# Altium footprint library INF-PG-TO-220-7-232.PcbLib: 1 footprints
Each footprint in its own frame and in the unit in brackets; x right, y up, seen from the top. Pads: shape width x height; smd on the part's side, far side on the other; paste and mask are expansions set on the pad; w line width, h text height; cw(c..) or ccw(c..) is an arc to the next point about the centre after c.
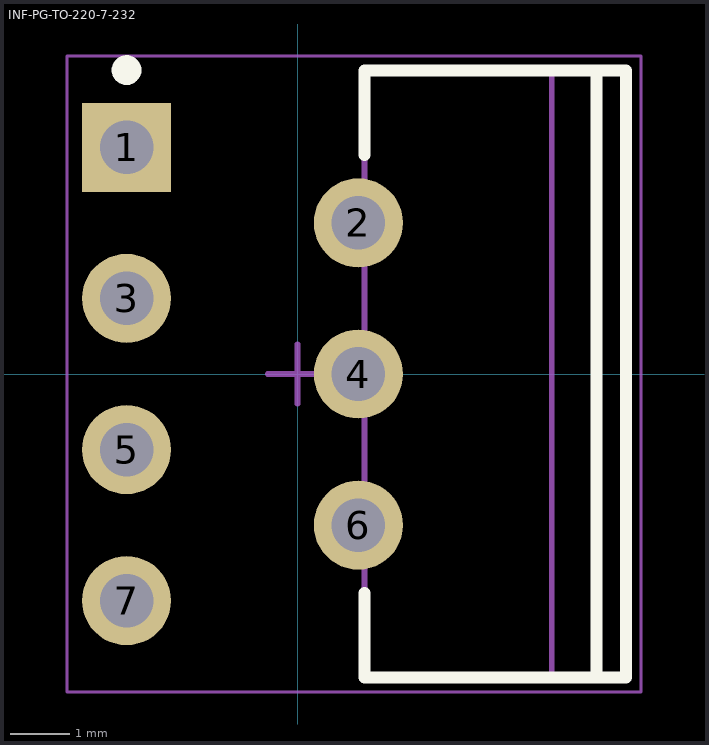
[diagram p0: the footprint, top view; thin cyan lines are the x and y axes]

## INF-PG-TO-220-7-232 [mm] "FM, 7-Leads, Body 10x4.4mm, Pitch 1.27mm"
height 20.02
pads (7):
  rect 1.5x1.5 hole 0.9: 1(-2.875,3.81)
  round 1.5 hole 0.9: 2(1.025,2.54) 3(-2.875,1.27) 4(1.025,0) 5(-2.875,-1.27) 6(1.025,-2.54) 7(-2.875,-3.81)
Top Overlay:
  circle w0.25: c-2.875,5.11 r0.125
  lines w0.2: 1.125,-3.683 1.125,-5.1 5.525,-5.1 5.525,5.1 1.125,5.1 1.125,3.683 ; 5.025,-5.1 5.025,5.1
Mechanical 13:
  lines w0.1: 4.275,-5.1 4.275,5.1 ; 1.125,-5.1 5.525,-5.1 5.525,5.1 1.125,5.1 1.125,-5.1
Mechanical 15:
  lines w0.05: -3.875,-5.35 5.775,-5.35 5.775,5.35 -3.875,5.35 -3.875,-5.35
  lines w0.1: -0.5,0 0.5,0 ; 0,-0.5 0,0.5
3D body: height 20.02, standoff 19.05, extent 4.275,-4.95 5.525,4.95
3D body: height 17.58, standoff 17.22, extent 4.275,-4.95 5.525,-1.825
3D body: height 17.58, standoff 17.22, extent 4.275,1.825 5.525,4.95
3D body: height 17.22, standoff 16.86, extent 4.275,-4.95 5.525,-1.825
3D body: height 17.22, standoff 16.86, extent 4.275,1.825 5.525,4.95
3D body: height 17.92, standoff 17.58, extent 4.275,-4.95 5.525,-1.79
3D body: height 17.92, standoff 17.58, extent 4.275,1.79 5.525,4.95
3D body: height 16.87, standoff 16.52, extent 4.275,-4.95 5.525,-1.79
3D body: height 16.87, standoff 16.52, extent 4.275,1.79 5.525,4.95
3D body: height 18.24, standoff 17.92, extent 4.275,-4.95 5.525,-1.686
3D body: height 18.24, standoff 17.92, extent 4.275,1.686 5.525,4.95
3D body: height 16.53, standoff 16.21, extent 4.275,-4.95 5.525,-1.686
3D body: height 16.53, standoff 16.21, extent 4.275,1.686 5.525,4.95
3D body: height 18.52, standoff 18.23, extent 4.275,-4.95 5.525,-1.517
3D body: height 18.52, standoff 18.23, extent 4.275,1.517 5.525,4.95
3D body: height 16.21, standoff 15.93, extent 4.275,-4.95 5.525,-1.517
3D body: height 16.21, standoff 15.93, extent 4.275,1.517 5.525,4.95
3D body: height 18.74, standoff 18.51, extent 4.275,-4.95 5.525,-1.29
3D body: height 18.74, standoff 18.51, extent 4.275,1.29 5.525,4.95
3D body: height 15.93, standoff 15.7, extent 4.275,-4.95 5.525,-1.29
3D body: height 15.93, standoff 15.7, extent 4.275,1.29 5.525,4.95
3D body: height 18.91, standoff 18.74, extent 4.275,-4.95 5.525,-1.014
3D body: height 18.91, standoff 18.74, extent 4.275,1.014 5.525,4.95
3D body: height 15.71, standoff 15.53, extent 4.275,-4.95 5.525,-1.014
3D body: height 15.71, standoff 15.53, extent 4.275,1.014 5.525,4.95
3D body: height 19.01, standoff 18.91, extent 4.275,-4.95 5.525,-0.698
3D body: height 19.01, standoff 18.91, extent 4.275,0.698 5.525,4.95
3D body: height 15.54, standoff 15.43, extent 4.275,-4.95 5.525,-0.698
3D body: height 15.54, standoff 15.43, extent 4.275,0.698 5.525,4.95
3D body: height 19.05, standoff 19.01, extent 4.275,-4.95 5.525,-0.356
3D body: height 19.05, standoff 19.01, extent 4.275,0.356 5.525,4.95
3D body: height 15.44, standoff 15.4, extent 4.275,-4.95 5.525,-0.356
3D body: height 15.44, standoff 15.4, extent 4.275,0.356 5.525,4.95
3D body: height 15.4, standoff 13.62, extent 4.275,-4.95 5.525,4.95
3D body: height 13.62, standoff 0.92, extent 1.125,-5.1 5.525,5.1
3D body: height 0, standoff -1.6, extent -3.125,-4.11 -2.625,-3.51
3D body: height 0.92, standoff 0.71, extent 3.075,-4.31 3.575,-3.31
3D body: height 0.71, standoff 0.21, extent -3.125,-4.31 3.575,-3.31
3D body: height 0.21, standoff 0, extent -3.125,-4.31 -2.625,-3.31
3D body: height 0, standoff -1.6, extent 2.625,-2.84 3.125,-2.24
3D body: height 0.92, standoff 0.71, extent 3.075,-3.04 3.575,-2.04
3D body: height 0.71, standoff 0.21, extent 2.625,-3.04 3.575,-2.04
3D body: height 0.21, standoff 0, extent 2.625,-3.04 3.125,-2.04
3D body: height 0, standoff -1.6, extent -3.125,-1.57 -2.625,-0.97
3D body: height 0.92, standoff 0.71, extent 3.075,-1.77 3.575,-0.77
3D body: height 0.71, standoff 0.21, extent -3.125,-1.77 3.575,-0.77
3D body: height 0.21, standoff 0, extent -3.125,-1.77 -2.625,-0.77
3D body: height 0, standoff -1.6, extent 2.625,-0.3 3.125,0.3
3D body: height 0.92, standoff 0.71, extent 3.075,-0.5 3.575,0.5
3D body: height 0.71, standoff 0.21, extent 2.625,-0.5 3.575,0.5
3D body: height 0.21, standoff 0, extent 2.625,-0.5 3.125,0.5
3D body: height 0, standoff -1.6, extent -3.125,0.97 -2.625,1.57
3D body: height 0.92, standoff 0.71, extent 3.075,0.77 3.575,1.77
3D body: height 0.71, standoff 0.21, extent -3.125,0.77 3.575,1.77
3D body: height 0.21, standoff 0, extent -3.125,0.77 -2.625,1.77
3D body: height 0, standoff -1.6, extent 2.625,2.24 3.125,2.84
3D body: height 0.92, standoff 0.71, extent 3.075,2.04 3.575,3.04
3D body: height 0.71, standoff 0.21, extent 2.625,2.04 3.575,3.04
3D body: height 0.21, standoff 0, extent 2.625,2.04 3.125,3.04
3D body: height 0, standoff -1.6, extent -3.125,3.51 -2.625,4.11
3D body: height 0.92, standoff 0.71, extent 3.075,3.31 3.575,4.31
3D body: height 0.71, standoff 0.21, extent -3.125,3.31 3.575,4.31
3D body: height 0.21, standoff 0, extent -3.125,3.31 -2.625,4.31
